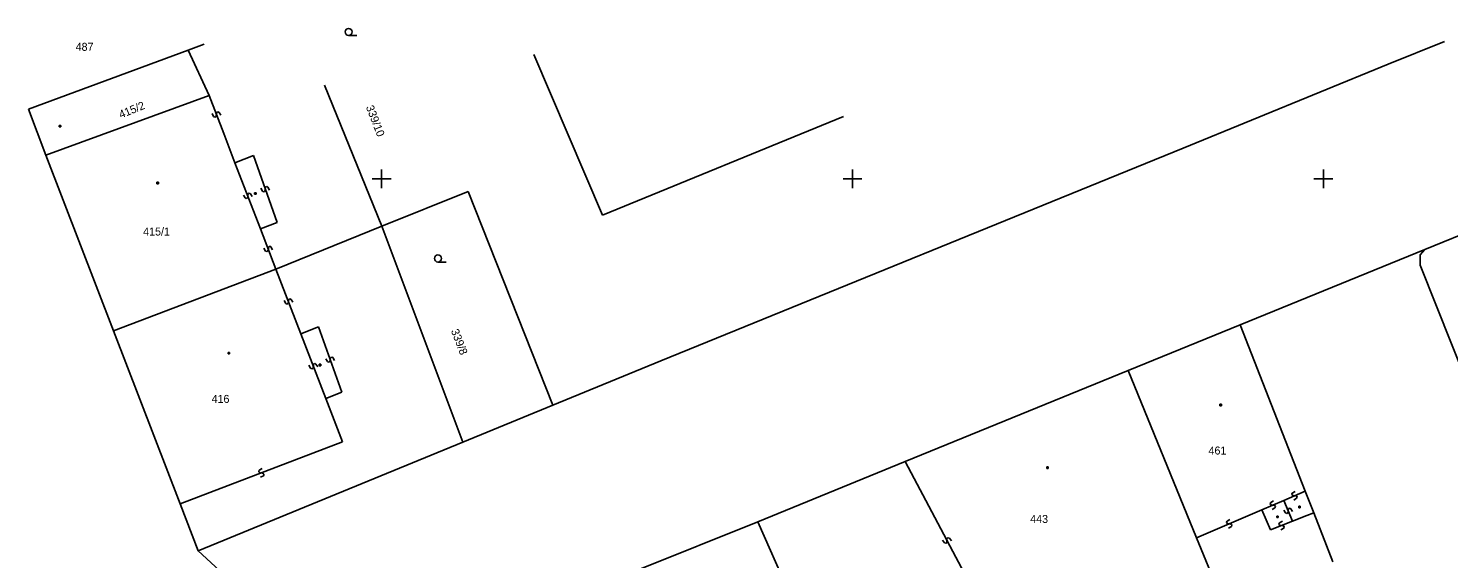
# Model space of a CAD drawing. Extents: x -492379 to -491966, y -1126153 to -1125860.
# Drawn here: x -492232.5 to -492142, y -1125894.2 to -1125860.4 of the extents above; entities that cross this region are included whole.
import ezdxf

# ---------------------------------------------------------------- set-up
doc = ezdxf.new("R2010")
doc.units = 0
doc.layers.add('katastrální mapa', color=7, linetype='Continuous')
doc.layers.add('síť', color=7, linetype='Continuous')

msp = doc.modelspace()

# ---------------------------------------------------------------- linework, layer by layer
at = {"layer": 'katastrální mapa'}
for p, q in [((-492212.1, -1125860.86), (-492211.57, -1125860.86)), ((-492232.5, -1125865.56), (-492222.33, -1125861.8)), ((-492222.33, -1125861.8), (-492221.3, -1125861.42)), ((-492222.33, -1125861.8), (-492220.99, -1125864.68)), ((-492142.29, -1125861.24), (-492145.87, -1125862.7)), ((-492200.3, -1125862.07), (-492195.93, -1125872.31)), ((-492145.87, -1125862.7), (-492158.94, -1125868.04)), ((-492143.53, -1125874.5), (-492116.5, -1125863.46)), ((-492213.63, -1125864.02), (-492209.99, -1125873.02)), ((-492231.38, -1125868.48), (-492220.99, -1125864.68)), ((-492220.99, -1125864.68), (-492220.06, -1125867.11)), ((-492232.5, -1125865.56), (-492231.38, -1125868.48)), ((-492220.7, -1125866.03), (-492220.8, -1125865.84)), ((-492220.62, -1125866.06), (-492220.7, -1125866.03)), ((-492220.57, -1125866.04), (-492220.62, -1125866.06)), ((-492220.53, -1125865.96), (-492220.57, -1125866.04)), ((-492220.52, -1125865.83), (-492220.53, -1125865.96)), ((-492220.48, -1125865.75), (-492220.52, -1125865.83)), ((-492220.43, -1125865.73), (-492220.48, -1125865.75)), ((-492220.35, -1125865.76), (-492220.43, -1125865.73)), ((-492220.25, -1125865.95), (-492220.35, -1125865.76)), ((-492195.93, -1125872.31), (-492180.57, -1125866.03)), ((-492230.53, -1125866.6), (-492230.44, -1125866.6)), ((-492230.53, -1125866.69), (-492230.53, -1125866.6)), ((-492230.44, -1125866.69), (-492230.53, -1125866.69)), ((-492230.44, -1125866.6), (-492230.44, -1125866.69)), ((-492220.06, -1125867.11), (-492219.34, -1125868.97)), ((-492192.21, -1125881.6), (-492158.94, -1125868.04)), ((-492231.38, -1125868.48), (-492227.07, -1125879.69)), ((-492219.34, -1125868.97), (-492218.17, -1125868.52)), ((-492219.34, -1125868.97), (-492217.71, -1125873.19)), ((-492218.17, -1125868.52), (-492216.66, -1125872.79)), ((-492224.31, -1125870.22), (-492224.22, -1125870.22)), ((-492224.31, -1125870.31), (-492224.31, -1125870.22)), ((-492224.22, -1125870.31), (-492224.31, -1125870.31)), ((-492224.22, -1125870.22), (-492224.22, -1125870.31)), ((-492218.09, -1125870.89), (-492218, -1125870.89)), ((-492218.09, -1125870.98), (-492218.09, -1125870.89)), ((-492218, -1125870.89), (-492218, -1125870.98)), ((-492217.59, -1125870.78), (-492217.69, -1125870.59)), ((-492217.52, -1125870.82), (-492217.59, -1125870.78)), ((-492217.46, -1125870.8), (-492217.52, -1125870.82)), ((-492217.42, -1125870.72), (-492217.46, -1125870.8)), ((-492217.41, -1125870.59), (-492217.42, -1125870.72)), ((-492217.37, -1125870.51), (-492217.41, -1125870.59)), ((-492217.31, -1125870.49), (-492217.37, -1125870.51)), ((-492217.24, -1125870.53), (-492217.31, -1125870.49)), ((-492217.14, -1125870.72), (-492217.24, -1125870.53)), ((-492209.99, -1125873.02), (-492204.48, -1125870.8)), ((-492204.48, -1125870.8), (-492199.1, -1125884.43)), ((-492218.7, -1125871.21), (-492218.8, -1125871.03)), ((-492218.62, -1125871.25), (-492218.7, -1125871.21)), ((-492218.57, -1125871.22), (-492218.62, -1125871.25)), ((-492218.53, -1125871.15), (-492218.57, -1125871.22)), ((-492218.52, -1125871.01), (-492218.53, -1125871.15)), ((-492218.48, -1125870.94), (-492218.52, -1125871.01)), ((-492218.43, -1125870.91), (-492218.48, -1125870.94)), ((-492218.35, -1125870.95), (-492218.43, -1125870.91)), ((-492218.25, -1125871.13), (-492218.35, -1125870.95)), ((-492218, -1125870.98), (-492218.09, -1125870.98)), ((-492217.71, -1125873.19), (-492216.66, -1125872.79)), ((-492217.71, -1125873.19), (-492216.73, -1125875.75)), ((-492216.73, -1125875.75), (-492209.99, -1125873.02)), ((-492209.99, -1125873.02), (-492206.86, -1125881.35)), ((-492217.39, -1125874.6), (-492217.5, -1125874.42)), ((-492217.21, -1125874.4), (-492217.23, -1125874.54)), ((-492217.18, -1125874.33), (-492217.21, -1125874.4)), ((-492217.12, -1125874.3), (-492217.18, -1125874.33)), ((-492217.05, -1125874.34), (-492217.12, -1125874.3)), ((-492216.94, -1125874.52), (-492217.05, -1125874.34)), ((-492155.3, -1125879.31), (-492143.53, -1125874.5)), ((-492217.32, -1125874.64), (-492217.39, -1125874.6)), ((-492217.26, -1125874.61), (-492217.32, -1125874.64)), ((-492217.23, -1125874.54), (-492217.26, -1125874.61)), ((-492206.41, -1125875.3), (-492205.88, -1125875.3)), ((-492227.07, -1125879.69), (-492216.73, -1125875.75)), ((-492216.73, -1125875.75), (-492215.14, -1125879.87)), ((-492216.11, -1125877.94), (-492216.21, -1125877.76)), ((-492216.03, -1125877.98), (-492216.11, -1125877.94)), ((-492215.98, -1125877.95), (-492216.03, -1125877.98)), ((-492215.94, -1125877.88), (-492215.98, -1125877.95)), ((-492215.93, -1125877.74), (-492215.94, -1125877.88)), ((-492215.89, -1125877.67), (-492215.93, -1125877.74)), ((-492215.84, -1125877.64), (-492215.89, -1125877.67)), ((-492215.76, -1125877.68), (-492215.84, -1125877.64)), ((-492215.66, -1125877.86), (-492215.76, -1125877.68)), ((-492227.07, -1125879.69), (-492222.83, -1125890.72)), ((-492215.14, -1125879.87), (-492214.02, -1125879.44)), ((-492215.14, -1125879.87), (-492213.56, -1125884)), ((-492214.02, -1125879.44), (-492212.53, -1125883.6)), ((-492162.43, -1125882.22), (-492155.3, -1125879.31)), ((-492155.3, -1125879.31), (-492151.16, -1125889.9)), ((-492219.77, -1125881.06), (-492219.68, -1125881.06)), ((-492219.77, -1125881.15), (-492219.77, -1125881.06)), ((-492219.68, -1125881.15), (-492219.77, -1125881.15)), ((-492219.68, -1125881.06), (-492219.68, -1125881.15)), ((-492213.45, -1125881.65), (-492213.55, -1125881.46)), ((-492213.38, -1125881.68), (-492213.45, -1125881.65)), ((-492213.32, -1125881.66), (-492213.38, -1125881.68)), ((-492213.28, -1125881.59), (-492213.32, -1125881.66)), ((-492213.27, -1125881.45), (-492213.28, -1125881.59)), ((-492213.23, -1125881.38), (-492213.27, -1125881.45)), ((-492213.17, -1125881.36), (-492213.23, -1125881.38)), ((-492213.1, -1125881.39), (-492213.17, -1125881.36)), ((-492213, -1125881.58), (-492213.1, -1125881.39)), ((-492206.86, -1125881.35), (-492204.82, -1125886.78)), ((-492199.1, -1125884.43), (-492192.21, -1125881.6)), ((-492214.52, -1125882.07), (-492214.63, -1125881.88)), ((-492214.45, -1125882.1), (-492214.52, -1125882.07)), ((-492214.39, -1125882.08), (-492214.45, -1125882.1)), ((-492214.36, -1125882), (-492214.39, -1125882.08)), ((-492214.34, -1125881.87), (-492214.36, -1125882)), ((-492214.31, -1125881.79), (-492214.34, -1125881.87)), ((-492214.25, -1125881.77), (-492214.31, -1125881.79)), ((-492214.18, -1125881.8), (-492214.25, -1125881.77)), ((-492214.07, -1125881.99), (-492214.18, -1125881.8)), ((-492213.97, -1125881.82), (-492213.88, -1125881.82)), ((-492213.97, -1125881.91), (-492213.97, -1125881.82)), ((-492213.88, -1125881.91), (-492213.97, -1125881.91)), ((-492213.88, -1125881.82), (-492213.88, -1125881.91)), ((-492176.64, -1125888.01), (-492162.43, -1125882.22)), ((-492162.43, -1125882.22), (-492158.08, -1125892.87)), ((-492213.56, -1125884), (-492212.53, -1125883.6)), ((-492213.56, -1125884), (-492212.49, -1125886.77)), ((-492204.82, -1125886.78), (-492199.1, -1125884.43)), ((-492156.59, -1125884.37), (-492156.5, -1125884.37)), ((-492156.59, -1125884.46), (-492156.59, -1125884.37)), ((-492156.5, -1125884.46), (-492156.59, -1125884.46)), ((-492156.5, -1125884.37), (-492156.5, -1125884.46)), ((-492222.83, -1125890.72), (-492212.49, -1125886.77)), ((-492221.68, -1125893.7), (-492204.82, -1125886.78)), ((-492186.04, -1125891.85), (-492176.64, -1125888.01)), ((-492176.64, -1125888.01), (-492171.32, -1125898.08)), ((-492217.79, -1125888.57), (-492217.83, -1125888.65)), ((-492217.83, -1125888.65), (-492217.8, -1125888.7)), ((-492217.8, -1125888.7), (-492217.73, -1125888.74)), ((-492217.61, -1125888.47), (-492217.79, -1125888.57)), ((-492217.73, -1125888.74), (-492217.59, -1125888.75)), ((-492217.53, -1125888.92), (-492217.71, -1125889.02)), ((-492217.59, -1125888.75), (-492217.52, -1125888.79)), ((-492217.49, -1125888.84), (-492217.53, -1125888.92)), ((-492217.52, -1125888.79), (-492217.49, -1125888.84)), ((-492167.63, -1125888.36), (-492167.54, -1125888.36)), ((-492167.63, -1125888.45), (-492167.63, -1125888.36)), ((-492167.54, -1125888.45), (-492167.63, -1125888.45)), ((-492167.54, -1125888.36), (-492167.54, -1125888.45)), ((-492222.83, -1125890.72), (-492221.68, -1125893.7)), ((-492153.92, -1125891.09), (-492152.53, -1125890.49)), ((-492153.36, -1125890.62), (-492153.39, -1125890.7)), ((-492153.39, -1125890.7), (-492153.37, -1125890.75)), ((-492153.37, -1125890.75), (-492153.29, -1125890.79)), ((-492153.18, -1125890.51), (-492153.36, -1125890.62)), ((-492153.29, -1125890.79), (-492153.16, -1125890.79)), ((-492153.16, -1125890.79), (-492153.08, -1125890.83)), ((-492152.53, -1125890.49), (-492151.16, -1125889.9)), ((-492152.53, -1125890.49), (-492151.96, -1125891.82)), ((-492151.98, -1125890.03), (-492152.01, -1125890.1)), ((-492152.01, -1125890.1), (-492151.99, -1125890.16)), ((-492151.99, -1125890.16), (-492151.91, -1125890.19)), ((-492151.8, -1125889.92), (-492151.98, -1125890.03)), ((-492151.91, -1125890.19), (-492151.78, -1125890.2)), ((-492151.71, -1125890.36), (-492151.89, -1125890.47)), ((-492151.78, -1125890.2), (-492151.7, -1125890.23)), ((-492151.68, -1125890.29), (-492151.71, -1125890.36)), ((-492151.7, -1125890.23), (-492151.68, -1125890.29)), ((-492151.16, -1125889.9), (-492150.62, -1125891.29)), ((-492158.08, -1125892.87), (-492153.92, -1125891.09)), ((-492155.96, -1125891.7), (-492156.14, -1125891.81)), ((-492153.92, -1125891.09), (-492153.37, -1125892.37)), ((-492153.09, -1125890.96), (-492153.27, -1125891.07)), ((-492153.06, -1125890.88), (-492153.09, -1125890.96)), ((-492153.08, -1125890.83), (-492153.06, -1125890.88)), ((-492152.97, -1125891.5), (-492152.88, -1125891.5)), ((-492152.97, -1125891.59), (-492152.97, -1125891.5)), ((-492152.88, -1125891.59), (-492152.97, -1125891.59)), ((-492152.88, -1125891.5), (-492152.88, -1125891.59)), ((-492152.41, -1125891.29), (-492152.52, -1125891.11)), ((-492152.34, -1125891.32), (-492152.41, -1125891.29)), ((-492152.28, -1125891.3), (-492152.34, -1125891.32)), ((-492152.25, -1125891.22), (-492152.28, -1125891.3)), ((-492152.24, -1125891.09), (-492152.25, -1125891.22)), ((-492152.21, -1125891.01), (-492152.24, -1125891.09)), ((-492152.15, -1125890.99), (-492152.21, -1125891.01)), ((-492152.08, -1125891.02), (-492152.15, -1125890.99)), ((-492151.97, -1125891.2), (-492152.08, -1125891.02)), ((-492151.96, -1125891.82), (-492151.06, -1125891.46)), ((-492151.57, -1125890.87), (-492151.48, -1125890.87)), ((-492151.57, -1125890.96), (-492151.57, -1125890.87)), ((-492151.48, -1125890.96), (-492151.57, -1125890.96)), ((-492151.48, -1125890.87), (-492151.48, -1125890.96)), ((-492151.06, -1125891.46), (-492150.62, -1125891.29)), ((-492150.62, -1125891.29), (-492149.4, -1125894.41)), ((-492193.65, -1125894.92), (-492186.04, -1125891.85)), ((-492186.04, -1125891.85), (-492183.14, -1125898.37)), ((-492156.14, -1125891.81), (-492156.17, -1125891.89)), ((-492156.17, -1125891.89), (-492156.15, -1125891.94)), ((-492156.15, -1125891.94), (-492156.07, -1125891.98)), ((-492156.07, -1125891.98), (-492155.93, -1125891.98)), ((-492155.86, -1125892.15), (-492156.04, -1125892.26)), ((-492155.93, -1125891.98), (-492155.85, -1125892.02)), ((-492155.83, -1125892.07), (-492155.86, -1125892.15)), ((-492155.85, -1125892.02), (-492155.83, -1125892.07)), ((-492153.37, -1125892.37), (-492151.96, -1125891.82)), ((-492152.8, -1125891.92), (-492152.83, -1125892)), ((-492152.83, -1125892), (-492152.81, -1125892.05)), ((-492152.81, -1125892.05), (-492152.73, -1125892.09)), ((-492152.61, -1125891.82), (-492152.8, -1125891.92)), ((-492152.73, -1125892.09), (-492152.6, -1125892.1)), ((-492152.53, -1125892.27), (-492152.72, -1125892.37)), ((-492152.6, -1125892.1), (-492152.52, -1125892.14)), ((-492152.5, -1125892.19), (-492152.53, -1125892.27)), ((-492152.52, -1125892.14), (-492152.5, -1125892.19)), ((-492174.14, -1125893.2), (-492174.26, -1125893.02)), ((-492174.06, -1125893.22), (-492174.14, -1125893.2)), ((-492174, -1125893.19), (-492174.06, -1125893.22)), ((-492173.98, -1125893.11), (-492174, -1125893.19)), ((-492173.96, -1125892.9), (-492173.98, -1125892.98)), ((-492173.98, -1125892.98), (-492173.98, -1125893.11)), ((-492173.9, -1125892.87), (-492173.96, -1125892.9)), ((-492173.82, -1125892.89), (-492173.9, -1125892.87)), ((-492173.7, -1125893.07), (-492173.82, -1125892.89)), ((-492158.08, -1125892.87), (-492156.21, -1125897.45)), ((-492221.68, -1125893.7), (-492209.77, -1125904.73))]:
    msp.add_line(p, q, dxfattribs=at)
msp.add_lwpolyline([(-492132.76, -1125898.44), (-492134.04, -1125898.97), (-492134.47, -1125898.88), (-492134.65, -1125898.6), (-492143.83, -1125875.5), (-492143.83, -1125874.84), (-492143.53, -1125874.5)], dxfattribs=at)
for centre in [(-492212.1, -1125860.635), (-492206.41, -1125875.075)]:
    msp.add_circle(centre, 0.225, dxfattribs=at)
at = {"layer": 'síť'}
for p, q in [((-492210, -1125869.4), (-492210, -1125870.6)), ((-492180, -1125869.4), (-492180, -1125870.6)), ((-492150, -1125869.4), (-492150, -1125870.6)), ((-492210.6, -1125870), (-492209.4, -1125870)), ((-492180.6, -1125870), (-492179.4, -1125870)), ((-492150.6, -1125870), (-492149.4, -1125870))]:
    msp.add_line(p, q, dxfattribs=at)

# ---------------------------------------------------------------- texts
at = {"layer": 'katastrální mapa'}
for s, p in [('487', (-492229.49, -1125861.84)), ('415/1', (-492225.19, -1125873.61)), ('416', (-492220.83, -1125884.28)), ('461', (-492157.32, -1125887.57)), ('443', (-492168.68, -1125891.93))]:
    msp.add_text(s, height=0.51, dxfattribs=at).set_placement(p)
for s, rotation, p in [('415/2', 22.23, (-492226.61, -1125866.16)), ('339/10', 291.177, (-492211.01, -1125865.42)), ('339/8', 291.177, (-492205.59, -1125879.68))]:
    msp.add_text(s, height=0.51, rotation=rotation, dxfattribs=at).set_placement(p)

doc.saveas('drawing.dxf')
